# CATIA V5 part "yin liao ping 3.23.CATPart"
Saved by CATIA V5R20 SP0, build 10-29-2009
Part number: 饮料瓶3.23
Material "Bright Plastic": density 1200 kg/m3, Young's modulus 2.2e+09 Pa, Poisson ratio 0.38, thermal expansion 6.84e-05 1/K
Material "Epoxy": density 1300 kg/m3, Young's modulus 3e+09 Pa, Poisson ratio 0.37, thermal expansion 6e-05 1/K
Bounding box of the stored display mesh (mm): x -25 to 25.2, y -25 to 25, z 0 to 110
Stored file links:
  E:\3D zuo ye\Bottle.CATPart\yin liao ping 3.23.CATPart
  E:\CATIAR20\win_b64\startup\materials\Catalog.CATMaterial
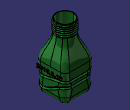
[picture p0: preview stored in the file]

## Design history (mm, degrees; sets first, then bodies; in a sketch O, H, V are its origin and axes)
Set1
  Sketch1 on xy-plane, origin (0, 0, 0), H (1, 0, 0), V (0, 1, 0)
    line L1 (25, 25) -> (25, -25)
    line L2 (25, -25) -> (-25, -25)
    line L3 (-25, -25) -> (-25, 25)
    line L4 (-25, 25) -> (25, 25)
    length L4 = 50
    length L1 = 50
    vertical: L1 V, L3 V
    horizontal: L2 H, L4 H
    equidistance: L1 L3 O, L2 L4 O
  Sketch2 on face of Pad1 from Sketch1.L1, origin (25, 0, 0), H (0, 1, 0), V (0, 0, 1)
    spline S1 through (-35, 35) (-17.8934, 30) (10, 35) (40, 30)
    point P1 (-35, 35)
    point P2 (-17.8934, 30)
    point P3 (10, 35)
    point P4 (40, 30)
    distance H P1 = 35
    distance P2 H = 30
    distance P3 H = 35
    distance P4 H = 30
    distance P1 V = 35
    distance P3 V = 10
    distance P4 V = 40
  Extrude1: Lim1 60, Lim2 60, Element1 Sketch2
  MultiSel1: CommonCtxFeats ({extract ExtractElem face of Pad1 from Sketch1.L3}; {extract ExtractElem face of Fillet1}; {extract ExtractElem face of Pad1 from Sketch1.L2}; {extract ExtractElem face of Fillet1}; {extract ExtractElem face of Pad1 from Sketch1.L1}; {extract ExtractElem face of Fillet1}; {extract ExtractElem face of Pad1 from Sketch1.L4}; {extract ExtractElem face of Fillet1})
  Join1: Elements ({intersect ToIntersect1 {extract ExtractElem face of Pad1 from Sketch1.L3}, ToIntersect2 Extrude1}; {intersect ToIntersect1 {extract ExtractElem face of Fillet1}, ToIntersect2 Extrude1}; {intersect ToIntersect1 {extract ExtractElem face of Pad1 from Sketch1.L2}, ToIntersect2 Extrude1}; {intersect ToIntersect1 {extract ExtractElem face of Fillet1}, ToIntersect2 Extrude1}; {intersect ToIntersect1 {extract ExtractElem face of Pad1 from Sketch1.L1}, ToIntersect2 Extrude1}; {intersect ToIntersect1 {extract ExtractElem face of Fillet1}, ToIntersect2 Extrude1}; {intersect ToIntersect1 {extract ExtractElem face of Pad1 from Sketch1.L4}, ToIntersect2 Extrude1}; {intersect ToIntersect1 {extract ExtractElem face of Fillet1}, ToIntersect2 Extrude1})
  Plane1: type Normal, Curve Join1, RefPoint vertex [face of MultiSel1 | face of MultiSel1]
  Circle1: type CtrRad, Start 0, End 180, Radius 2, Center vertex [face of MultiSel1 | face of MultiSel1], Support Plane1, FirstDirection (-1, 0, 0)
Body1 (main body), material "Bright Plastic"
  Pad1: profile Sketch1, direction (0, 0, 1), length 50
  Fillet1: on edge [face of Pad1 from Sketch1.L4 | face of Pad1 from Sketch1.L1]; edge [face of Pad1 from Sketch1.L1 | face of Pad1 from Sketch1.L2]; edge [face of Pad1 from Sketch1.L3 | face of Pad1 from Sketch1.L4]; edge [face of Pad1 from Sketch1.L2 | face of Pad1 from Sketch1.L3]
  Fillet2: radius 12, on start face of Pad1
  Plane2: type Offset, RefPlane end face of Pad1, Offset 40, reversed
  Sketch3 on Plane2, origin (0, 0, 90), H (1, 0, 0), V (0, -1, 0)
    circle A1 centre (0, 0) radius 15
    radius A1 = 15
  Pad2: profile Sketch3, direction (0, 0, 1), length 20
  Sketch4 on Plane2, origin (0, 0, 90), H (1, 0, 0), V (0, -1, 0)
    point P1 (15, 0)
    distance P1 V = 15
    coincidence: P1 H
  Sketch5 on end face of Pad1, origin (0, 0, 50), H (1, 0, 0), V (0, 1, 0)
    point P1 (25, 0)
    distance P1 V = 25
    coincidence: P1 H
  Loft1: solid, Sections ({boundary Boundary {extract ExtractElem start face of Pad2}}; {boundary Boundary {extract ExtractElem end face of Pad1}}), StartFace start face of Pad2, EndFace end face of Pad1
  Slot1: profile Circle1, centre curve Join1
  Sketch6 on face of Pad1 from Sketch1.L3, origin (-25, 0, 0), H (0, -1, 0), V (0, 0, 1)
    spline S1 through (-38.4747, 18.95) (-17.832, 26.3615) (2.1085, 16.4329) (34.547, 24.8232)
  Extrude2: Lim1 60, Lim2 60, Element1 Sketch6
  MultiSel2: CommonCtxFeats ({extract ExtractElem face of Pad1 from Sketch1.L3}; {extract ExtractElem face of Fillet1}; {extract ExtractElem face of Pad1 from Sketch1.L2}; {extract ExtractElem face of Fillet1}; {extract ExtractElem face of Pad1 from Sketch1.L1}; {extract ExtractElem face of Fillet1}; {extract ExtractElem face of Pad1 from Sketch1.L4}; {extract ExtractElem face of Fillet1})
  Join2: Elements ({intersect ToIntersect1 {extract ExtractElem face of Pad1 from Sketch1.L3}, ToIntersect2 Extrude2}; {intersect ToIntersect1 {extract ExtractElem face of Fillet1}, ToIntersect2 Extrude2}; {intersect ToIntersect1 {extract ExtractElem face of Pad1 from Sketch1.L2}, ToIntersect2 Extrude2}; {intersect ToIntersect1 {extract ExtractElem face of Fillet1}, ToIntersect2 Extrude2}; {intersect ToIntersect1 {extract ExtractElem face of Pad1 from Sketch1.L1}, ToIntersect2 Extrude2}; {intersect ToIntersect1 {extract ExtractElem face of Fillet1}, ToIntersect2 Extrude2}; {intersect ToIntersect1 {extract ExtractElem face of Pad1 from Sketch1.L4}, ToIntersect2 Extrude2}; {intersect ToIntersect1 {extract ExtractElem face of Fillet1}, ToIntersect2 Extrude2})
  Plane3: type Normal, Curve Join2, RefPoint vertex [face of MultiSel2 | face of MultiSel2]
  Circle2: type CtrRad, Start 0, End 180, Radius 2, Center vertex [face of MultiSel2 | face of MultiSel2], Support Plane3, FirstDirection (0, -1, 0)
  Slot2: profile Circle2, centre curve Join2
  Shell1: IntOffset 1, Face end face of Pad2, ExtOffset 0
  Point1: type OnSurface, Support face of Pad2 from Sketch3.A1, Length 2, Direction (0, 0, 1), RefPoint Sketch4
  Helix1: Direction Z axis, RefPoint Point1, Pitch 3, Height 16, TaperAngle 0
  Line1: type PtDir, RefPoint vertex of Helix1, Direction (0, 1, 0), Start 0, End 10
  Point2: type OnCurve, Support Helix1, Length -5.702, RefPoint vertex of Helix1
  Connect1: Curve1 Line1, Point1 vertex of Line1, Tension1 1, Curve2 Helix1, Point2 Point2, Tension2 1
  Point3: type OnCurve, Support Connect1, RefPoint Point1, Length -5.807
  Line2: type PtDir, RefPoint Point1, Direction (1, 0, 0), Start 0, End 10
  Connect2: Curve1 Line2, Point1 vertex of Line2, Tension1 1, Curve2 Connect1, Point2 Point3, Tension2 1
  Plane4: type Normal, Curve Connect2, RefPoint vertex of Connect1
  Circle3: type CtrRad, Start 0, End 180, Radius 1, Center vertex of Connect1, Support Plane4, FirstDirection (1, 0, 0)
  Rib1: profile Circle3, centre curve Connect2
  Body2
    Sketch7 on Plane2, origin (0, 0, 90), H (1, 0, 0), V (0, -1, 0)
      circle A1 centre (0, 0) radius 14
      radius A1 = 14
    Pad3: profile Sketch7, direction (0, 0, 1), length 20
  Remove1: tool Body2
Body3, material "Epoxy"
  Sketch8 on face of Pad1 from Sketch1.L1, origin (25, 0, 0), H (0, 1, 0), V (0, 0, 1)
    polyline C1
    polyline C2
    polyline C3
    polyline C4
    polyline C5
    polyline C6
    polyline C7
    polyline C8
    polyline C9
    polyline C10
    polyline C11
  Pad4: profile Sketch8, direction (1, 0, 0), length 0.2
